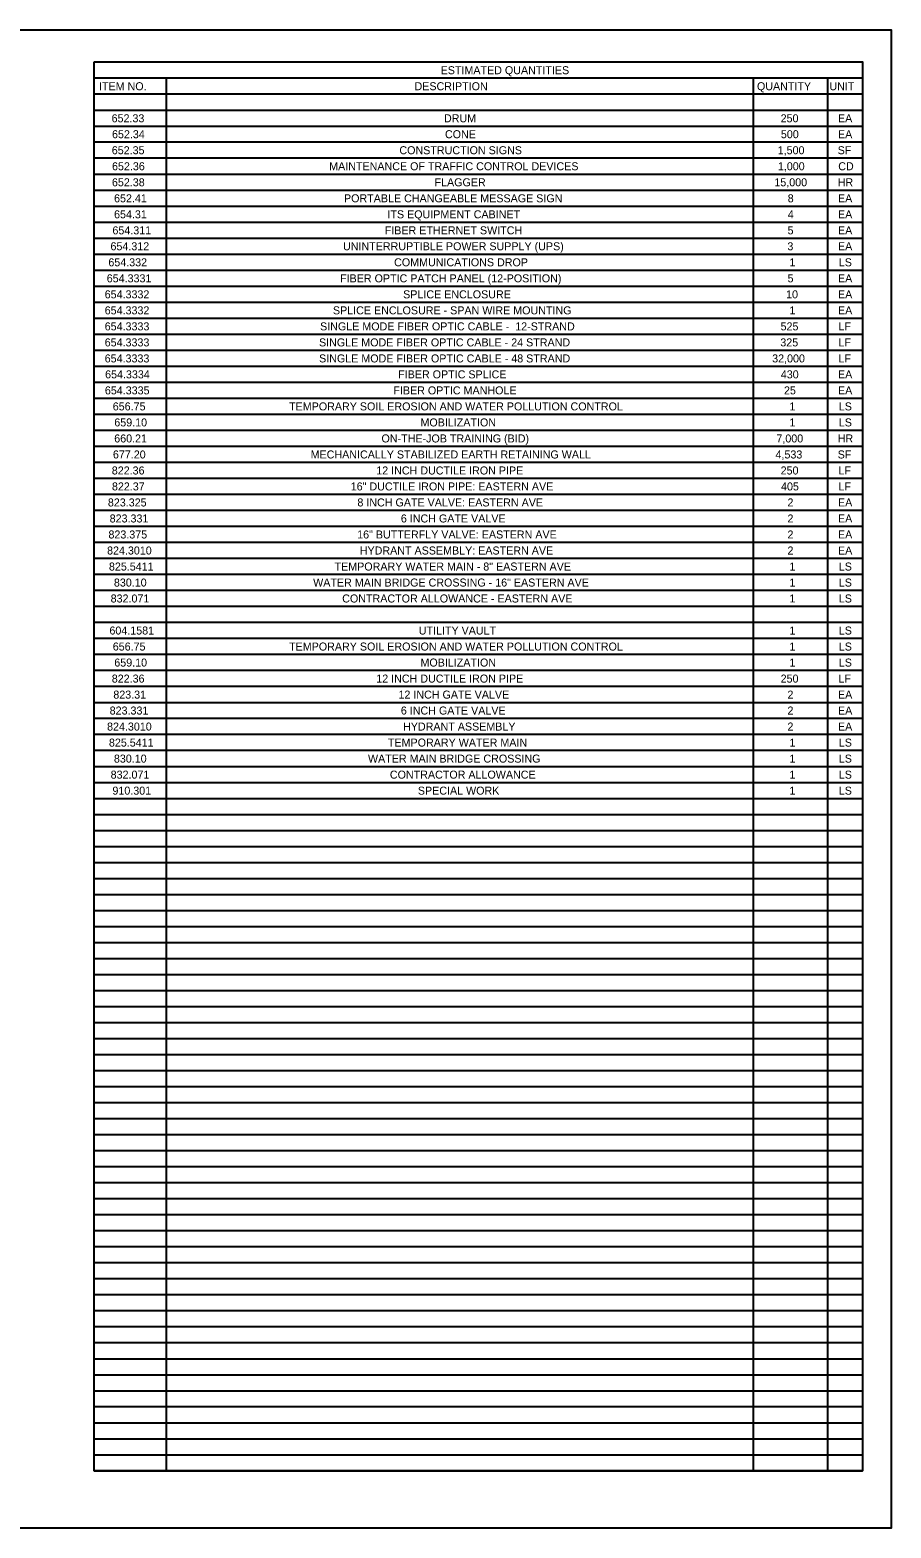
# Model space of a CAD drawing. Extents: x -18.7 to 5.6, y -2.7 to 4.
# Drawn here: x -14.366 to -13.308, y 2.172 to 4.014 of the extents above; entities that cross this region are included whole.
import ezdxf

# ---------------------------------------------------------------- set-up
doc = ezdxf.new("R2010")
doc.units = 0
doc.layers.add('ANNOTATION', color=7, linetype='Continuous')
doc.layers.add('BORDER', color=7, linetype='Continuous')

msp = doc.modelspace()

# ---------------------------------------------------------------- linework, layer by layer
at = {"layer": 'ANNOTATION'}
msp.add_lwpolyline([(-17.663, 4.0141), (-13.3075, 4.0141), (-13.3075, 2.1719), (-17.663, 2.1719)], close=True, dxfattribs=at)
at = {"layer": 'BORDER'}
for p, q in [((-14.2869, 3.9551), (-13.3426, 3.9551)), ((-14.1983, 3.9551), (-14.1983, 2.2424)), ((-13.477, 3.9551), (-13.477, 2.2424)), ((-13.3856, 3.9551), (-13.3856, 2.2424)), ((-14.2869, 3.9354), (-13.3426, 3.9354)), ((-14.2869, 3.9157), (-13.3426, 3.9157)), ((-14.2869, 3.896), (-13.3426, 3.896)), ((-14.2869, 3.8764), (-13.3426, 3.8764)), ((-14.2869, 3.8567), (-13.3426, 3.8567)), ((-14.2869, 3.837), (-13.3426, 3.837)), ((-14.2869, 3.8173), (-13.3426, 3.8173)), ((-14.2869, 3.7976), (-13.3426, 3.7976)), ((-14.2869, 3.7779), (-13.3426, 3.7779)), ((-14.2869, 3.7582), (-13.3426, 3.7582)), ((-14.2869, 3.7386), (-13.3426, 3.7386)), ((-14.2869, 3.7189), (-13.3426, 3.7189)), ((-14.2869, 3.6992), (-13.3426, 3.6992)), ((-14.2869, 3.6795), (-13.3426, 3.6795)), ((-14.2869, 3.6598), (-13.3426, 3.6598)), ((-14.2869, 3.6401), (-13.3426, 3.6401)), ((-14.2869, 3.6204), (-13.3426, 3.6204)), ((-14.2869, 3.6008), (-13.3426, 3.6008)), ((-14.2869, 3.5811), (-13.3426, 3.5811)), ((-14.2869, 3.5614), (-13.3426, 3.5614)), ((-14.2869, 3.5417), (-13.3426, 3.5417)), ((-14.2869, 3.522), (-13.3426, 3.522)), ((-14.2869, 3.5023), (-13.3426, 3.5023)), ((-14.2869, 3.4826), (-13.3426, 3.4826)), ((-14.2869, 3.463), (-13.3426, 3.463)), ((-14.2869, 3.4433), (-13.3426, 3.4433)), ((-14.2869, 3.4236), (-13.3426, 3.4236)), ((-14.2869, 3.4039), (-13.3426, 3.4039)), ((-14.2869, 3.3842), (-13.3426, 3.3842)), ((-14.2869, 3.3645), (-13.3426, 3.3645)), ((-14.2869, 3.3448), (-13.3426, 3.3448)), ((-14.2869, 3.3251), (-13.3426, 3.3251)), ((-14.2869, 3.3055), (-13.3426, 3.3055)), ((-14.2869, 3.2858), (-13.3426, 3.2858)), ((-14.2869, 3.2661), (-13.3426, 3.2661)), ((-14.2869, 3.2464), (-13.3426, 3.2464)), ((-14.2869, 3.2267), (-13.3426, 3.2267)), ((-14.2869, 3.207), (-13.3426, 3.207)), ((-14.2869, 3.1873), (-13.3426, 3.1873)), ((-14.2869, 3.1677), (-13.3426, 3.1677)), ((-14.2869, 3.148), (-13.3426, 3.148)), ((-14.2869, 3.1283), (-13.3426, 3.1283)), ((-14.2869, 3.1086), (-13.3426, 3.1086)), ((-14.2869, 3.0889), (-13.3426, 3.0889)), ((-14.2869, 3.0692), (-13.3426, 3.0692)), ((-14.2869, 3.0495), (-13.3426, 3.0495)), ((-14.2869, 3.0299), (-13.3426, 3.0299)), ((-14.2869, 3.0102), (-13.3426, 3.0102)), ((-14.2869, 2.9905), (-13.3426, 2.9905)), ((-14.2869, 2.9708), (-13.3426, 2.9708)), ((-14.2869, 2.9511), (-13.3426, 2.9511)), ((-14.2869, 2.9314), (-13.3426, 2.9314)), ((-14.2869, 2.9117), (-13.3426, 2.9117)), ((-14.2869, 2.8921), (-13.3426, 2.8921)), ((-14.2869, 2.8724), (-13.3426, 2.8724)), ((-14.2869, 2.8527), (-13.3426, 2.8527)), ((-14.2869, 2.833), (-13.3426, 2.833)), ((-14.2869, 2.8133), (-13.3426, 2.8133)), ((-14.2869, 2.7936), (-13.3426, 2.7936)), ((-14.2869, 2.7739), (-13.3426, 2.7739)), ((-14.2869, 2.7543), (-13.3426, 2.7543)), ((-14.2869, 2.7346), (-13.3426, 2.7346)), ((-14.2869, 2.7149), (-13.3426, 2.7149)), ((-14.2869, 2.6952), (-13.3426, 2.6952)), ((-14.2869, 2.6755), (-13.3426, 2.6755)), ((-14.2869, 2.6558), (-13.3426, 2.6558)), ((-14.2869, 2.6361), (-13.3426, 2.6361)), ((-14.2869, 2.6165), (-13.3426, 2.6165)), ((-14.2869, 2.5968), (-13.3426, 2.5968)), ((-14.2869, 2.5771), (-13.3426, 2.5771)), ((-14.2869, 2.5574), (-13.3426, 2.5574)), ((-14.2869, 2.5377), (-13.3426, 2.5377)), ((-14.2869, 2.518), (-13.3426, 2.518)), ((-14.2869, 2.4983), (-13.3426, 2.4983)), ((-14.2869, 2.4787), (-13.3426, 2.4787)), ((-14.2869, 2.459), (-13.3426, 2.459)), ((-14.2869, 2.4393), (-13.3426, 2.4393)), ((-14.2869, 2.4196), (-13.3426, 2.4196)), ((-14.2869, 2.3999), (-13.3426, 2.3999)), ((-14.2869, 2.3802), (-13.3426, 2.3802)), ((-14.2869, 2.3605), (-13.3426, 2.3605)), ((-14.2869, 2.3408), (-13.3426, 2.3408)), ((-14.2869, 2.3212), (-13.3426, 2.3212)), ((-14.2869, 2.3015), (-13.3426, 2.3015)), ((-14.2869, 2.2818), (-13.3426, 2.2818)), ((-14.2869, 2.2621), (-13.3426, 2.2621)), ((-14.2869, 2.2424), (-13.3426, 2.2424))]:
    msp.add_line(p, q, dxfattribs=at)
msp.add_lwpolyline([(-14.2869, 3.9748), (-13.3426, 3.9748), (-13.3426, 2.2424), (-14.2869, 2.2424)], close=True, dxfattribs=at)

# ---------------------------------------------------------------- texts
at = {"layer": 'ANNOTATION'}
for s, height, p in [('652.33', 0.00984, (-14.2655, 3.9006)), ('DRUM', 0.00984, (-13.857, 3.9006)), ('250', 0.00984, (-13.4432, 3.9006)), ('EA', 0.00984, (-13.3727, 3.9006)), ('652.34', 0.00984, (-14.265, 3.881)), ('CONE', 0.00984, (-13.8558, 3.881)), ('500', 0.00984, (-13.4429, 3.881)), ('EA', 0.00984, (-13.3727, 3.881)), ('652.35', 0.00984, (-14.2653, 3.8613)), ('CONSTRUCTION SIGNS', 0.009843, (-13.9118, 3.8613)), ('1,500', 0.00984, (-13.4468, 3.8613)), ('SF', 0.00984, (-13.3731, 3.8613)), ('652.36', 0.00984, (-14.265, 3.8416)), ('MAINTENANCE OF TRAFFIC CONTROL DEVICES', 0.009843, (-13.9981, 3.8416)), ('1,000', 0.00984, (-13.4466, 3.8416)), ('CD', 0.00984, (-13.3724, 3.8416)), ('652.38', 0.00984, (-14.2651, 3.8219)), ('FLAGGER', 0.00984, (-13.8686, 3.8219)), ('15,000', 0.00984, (-13.4509, 3.8219)), ('HR', 0.00984, (-13.3731, 3.8219)), ('652.41', 0.00984, (-14.2625, 3.8022)), ('PORTABLE CHANGEABLE MESSAGE SIGN', 0.009843, (-13.9799, 3.8022)), ('8', 0.00984, (-13.4345, 3.8022)), ('EA', 0.00984, (-13.3727, 3.8022)), ('654.31', 0.00984, (-14.2625, 3.7825)), ('ITS EQUIPMENT CABINET  ', 0.009843, (-13.9265, 3.7825)), ('4', 0.00984, (-13.4344, 3.7825)), ('EA', 0.00984, (-13.3727, 3.7825)), ('654.311', 0.00984, (-14.2645, 3.7628)), ('FIBER ETHERNET SWITCH ', 0.009843, (-13.9298, 3.7628)), ('5', 0.00984, (-13.4347, 3.7628)), ('EA', 0.00984, (-13.3727, 3.7628)), ('654.312', 0.00984, (-14.2669, 3.7432)), ('UNINTERRUPTIBLE POWER SUPPLY (UPS)', 0.009843, (-13.9811, 3.7432)), ('3', 0.00984, (-13.4349, 3.7432)), ('EA', 0.00984, (-13.3727, 3.7432)), ('654.332', 0.00984, (-14.2695, 3.7235)), ('COMMUNICATIONS DROP', 0.009843, (-13.9183, 3.7235)), ('1', 0.00984, (-13.4324, 3.7235)), ('LS', 0.00984, (-13.3717, 3.7235)), ('654.3331', 0.00984, (-14.2715, 3.7038)), ('FIBER OPTIC PATCH PANEL (12-POSITION)', 0.009843, (-13.9847, 3.7038)), ('5', 0.00984, (-13.4347, 3.7038)), ('EA', 0.00984, (-13.3727, 3.7038)), ('654.3332', 0.00984, (-14.274, 3.6841)), ('SPLICE ENCLOSURE', 0.009843, (-13.9072, 3.6841)), ('10', 0.00984, (-13.4365, 3.6841)), ('EA', 0.00984, (-13.3727, 3.6841)), ('654.3332', 0.00984, (-14.274, 3.6644)), ('SPLICE ENCLOSURE - SPAN WIRE MOUNTING', 0.009843, (-13.9935, 3.6644)), ('1', 0.00984, (-13.4324, 3.6644)), ('EA', 0.00984, (-13.3727, 3.6644)), ('654.3333', 0.00984, (-14.274, 3.6447)), ('SINGLE MODE FIBER OPTIC CABLE -  12-STRAND', 0.009843, (-14.0093, 3.6447)), ('525', 0.00984, (-13.4433, 3.6447)), ('LF', 0.00984, (-13.3721, 3.6447)), ('654.3333', 0.00984, (-14.274, 3.625)), ('SINGLE MODE FIBER OPTIC CABLE - 24 STRAND', 0.009843, (-14.0106, 3.625)), ('325', 0.00984, (-13.4436, 3.625)), ('LF', 0.00984, (-13.3721, 3.625)), ('654.3333', 0.00984, (-14.274, 3.6053)), ('SINGLE MODE FIBER OPTIC CABLE - 48 STRAND', 0.009843, (-14.0105, 3.6053)), ('32,000', 0.00984, (-13.4536, 3.6053)), ('LF', 0.00984, (-13.3721, 3.6053)), ('654.3334', 0.00984, (-14.2735, 3.5857)), ('FIBER OPTIC SPLICE ', 0.009843, (-13.9133, 3.5857)), ('430', 0.00984, (-13.443, 3.5857)), ('EA', 0.00984, (-13.3727, 3.5857)), ('654.3335', 0.00984, (-14.2738, 3.566)), ('FIBER OPTIC MANHOLE ', 0.009843, (-13.9192, 3.566)), ('25', 0.00984, (-13.4391, 3.566)), ('EA', 0.00984, (-13.3727, 3.566)), ('656.75', 0.00984, (-14.2641, 3.5463)), ('TEMPORARY SOIL EROSION AND WATER POLLUTION CONTROL', 0.009843, (-14.0474, 3.5463)), ('1', 0.00984, (-13.4324, 3.5463)), ('LS', 0.00984, (-13.3717, 3.5463)), ('659.10', 0.00984, (-14.2622, 3.5266)), ('MOBILIZATION', 0.009843, (-13.8859, 3.5266)), ('1', 0.00984, (-13.4324, 3.5266)), ('LS', 0.00984, (-13.3717, 3.5266)), ('660.21', 0.00984, (-14.2623, 3.5069)), ('ON-THE-JOB TRAINING (BID)', 0.009843, (-13.9338, 3.5069)), ('7,000', 0.00984, (-13.4484, 3.5069)), ('HR', 0.00984, (-13.3731, 3.5069)), ('677.20', 0.00984, (-14.2639, 3.4872)), ('MECHANICALLY STABILIZED EARTH RETAINING WALL', 0.009843, (-14.0209, 3.4872)), ('4,533', 0.00984, (-13.4495, 3.4872)), ('SF', 0.00984, (-13.3731, 3.4872)), ('822.36', 0.00984, (-14.2653, 3.4675)), ('12 INCH DUCTILE IRON PIPE', 0.009843, (-13.9402, 3.4675)), ('250', 0.00984, (-13.4432, 3.4675)), ('LF', 0.00984, (-13.3721, 3.4675)), ('822.37', 0.00984, (-14.2651, 3.4479)), ('16" DUCTILE IRON PIPE: EASTERN AVE', 0.009843, (-13.9716, 3.4479)), ('405', 0.00984, (-13.4427, 3.4479)), ('LF', 0.00984, (-13.3721, 3.4479)), ('823.325', 0.00984, (-14.2701, 3.4282)), ('8 INCH GATE VALVE: EASTERN AVE', 0.009843, (-13.9634, 3.4282)), ('2', 0.00984, (-13.4348, 3.4282)), ('EA', 0.00984, (-13.3727, 3.4282)), ('823.331', 0.00984, (-14.2679, 3.4085)), ('6 INCH GATE VALVE', 0.009843, (-13.91, 3.4085)), ('2', 0.00984, (-13.4348, 3.4085)), ('EA', 0.00984, (-13.3727, 3.4085)), ('823.375', 0.00984, (-14.2694, 3.3888)), ('16" BUTTERFLY VALVE: EASTERN AVE', 0.009843, (-13.9637, 3.3888)), ('2', 0.00984, (-13.4348, 3.3888)), ('EA', 0.00984, (-13.3727, 3.3888)), ('824.3010', 0.00984, (-14.2711, 3.3691)), ('HYDRANT ASSEMBLY: EASTERN AVE', 0.009843, (-13.9605, 3.3691)), ('2', 0.00984, (-13.4348, 3.3691)), ('EA', 0.00984, (-13.3727, 3.3691)), ('825.5411', 0.00984, (-14.2688, 3.3494)), ('TEMPORARY WATER MAIN - 8" EASTERN AVE', 0.009843, (-13.9915, 3.3494)), ('1', 0.00984, (-13.4324, 3.3494)), ('LS', 0.00984, (-13.3717, 3.3494)), ('830.10', 0.00984, (-14.2627, 3.3297)), ('WATER MAIN BRIDGE CROSSING - 16" EASTERN AVE', 0.009843, (-14.0178, 3.3297)), ('1', 0.00984, (-13.4324, 3.3297)), ('LS', 0.00984, (-13.3717, 3.3297)), ('832.071', 0.00984, (-14.2667, 3.3101)), ('CONTRACTOR ALLOWANCE - EASTERN AVE', 0.009843, (-13.9821, 3.3101)), ('1', 0.00984, (-13.4324, 3.3101)), ('LS', 0.00984, (-13.3717, 3.3101)), ('604.1581', 0.00984, (-14.2682, 3.2707)), ('UTILITY VAULT', 0.009843, (-13.888, 3.2707)), ('1', 0.00984, (-13.4324, 3.2707)), ('LS', 0.00984, (-13.3717, 3.2707)), ('656.75', 0.00984, (-14.2641, 3.251)), ('TEMPORARY SOIL EROSION AND WATER POLLUTION CONTROL', 0.009843, (-14.0474, 3.251)), ('1', 0.00984, (-13.4324, 3.251)), ('LS', 0.00984, (-13.3717, 3.251)), ('659.10', 0.00984, (-14.2622, 3.2313)), ('MOBILIZATION', 0.009843, (-13.8859, 3.2313)), ('1', 0.00984, (-13.4324, 3.2313)), ('LS', 0.00984, (-13.3717, 3.2313)), ('822.36', 0.00984, (-14.2653, 3.2116)), ('12 INCH DUCTILE IRON PIPE', 0.009843, (-13.9402, 3.2116)), ('250', 0.00984, (-13.4432, 3.2116)), ('LF', 0.00984, (-13.3721, 3.2116)), ('823.31', 0.00984, (-14.2634, 3.1919)), ('12 INCH GATE VALVE', 0.009843, (-13.9129, 3.1919)), ('2', 0.00984, (-13.4348, 3.1919)), ('EA', 0.00984, (-13.3727, 3.1919)), ('823.331', 0.00984, (-14.2679, 3.1723)), ('6 INCH GATE VALVE', 0.009843, (-13.91, 3.1723)), ('2', 0.00984, (-13.4348, 3.1723)), ('EA', 0.00984, (-13.3727, 3.1723)), ('824.3010', 0.00984, (-14.2711, 3.1526)), ('HYDRANT ASSEMBLY', 0.009843, (-13.9073, 3.1526)), ('2', 0.00984, (-13.4348, 3.1526)), ('EA', 0.00984, (-13.3727, 3.1526)), ('825.5411', 0.00984, (-14.2688, 3.1329)), ('TEMPORARY WATER MAIN', 0.009843, (-13.9259, 3.1329)), ('1', 0.00984, (-13.4324, 3.1329)), ('LS', 0.00984, (-13.3717, 3.1329)), ('830.10', 0.00984, (-14.2627, 3.1132)), ('WATER MAIN BRIDGE CROSSING', 0.009843, (-13.9504, 3.1132)), ('1', 0.00984, (-13.4324, 3.1132)), ('LS', 0.00984, (-13.3717, 3.1132)), ('832.071', 0.00984, (-14.2667, 3.0935)), ('CONTRACTOR ALLOWANCE', 0.009843, (-13.9235, 3.0935)), ('1', 0.00984, (-13.4324, 3.0935)), ('LS', 0.00984, (-13.3717, 3.0935)), ('910.301', 0.00984, (-14.2645, 3.0738)), ('SPECIAL WORK', 0.009843, (-13.8891, 3.0738)), ('1', 0.00984, (-13.4324, 3.0738)), ('LS', 0.00984, (-13.3717, 3.0738))]:
    msp.add_text(s, height=height, dxfattribs=at).set_placement(p)
at = {"layer": 'BORDER'}
for s, height, p in [('ESTIMATED QUANTITIES', 0.009843, (-13.8611, 3.9597)), ('ITEM NO.', 0.00984, (-14.281, 3.94)), ('DESCRIPTION', 0.009843, (-13.8932, 3.94)), ('QUANTITY', 0.00984, (-13.4723, 3.94)), ('UNIT', 0.00984, (-13.3833, 3.94))]:
    msp.add_text(s, height=height, dxfattribs=at).set_placement(p)

doc.saveas('drawing.dxf')
